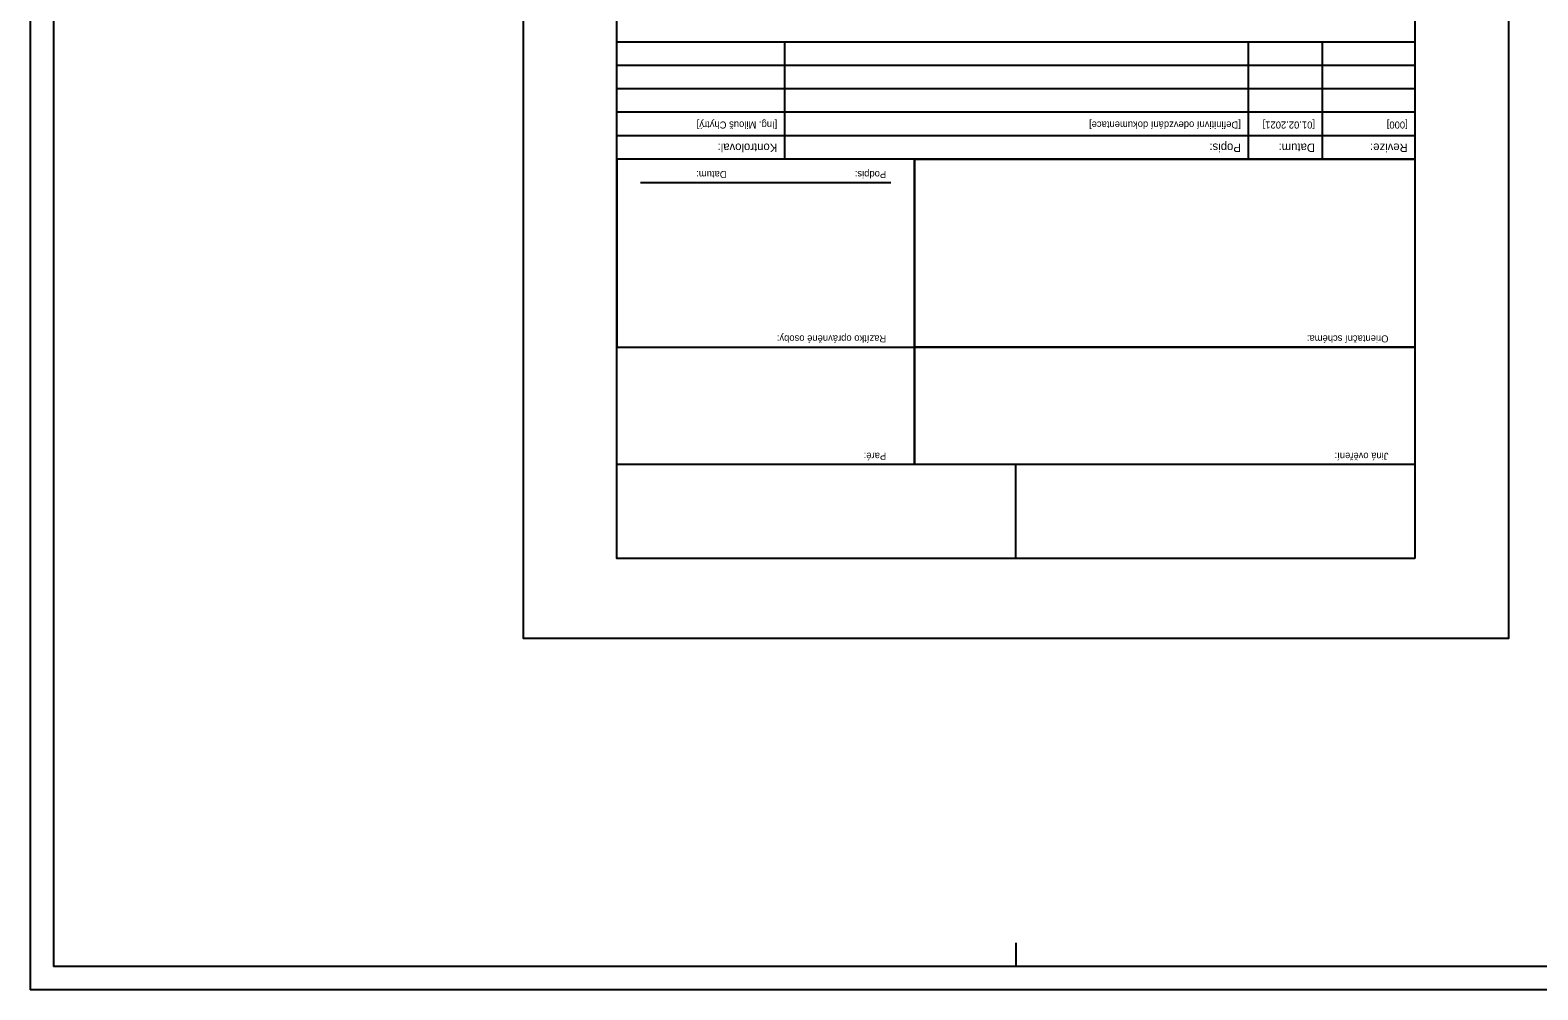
# Model space of a CAD drawing. Extents: x -751921 to -750661, y -1114881 to -1114287.
# Drawn here: x -751921.1 to -751599.9, y -1114880.7 to -1114676.3 of the extents above; entities that cross this region are included whole.
import ezdxf

# ---------------------------------------------------------------- set-up
doc = ezdxf.new("R2010")
doc.units = 0
doc.layers.add('Default', color=7, linetype='Continuous')
doc.layers.add('tisk', color=7, linetype='Continuous')

# ---------------------------------------------------------------- blocks, each defined once
blk = doc.blocks.new('ZMENY_1')
at = {"layer": 'Default'}
for p, q in [((-1502.5, 0), (-1502.5, 250)), ((-1344.5, 0), (-1344.5, 250)), ((-357, 0), (-357, 250)), ((-1700, 200), (0, 200)), ((-1700, 150), (0, 150)), ((-1700, 100), (0, 100)), ((-1700, 50), (0, 50))]:
    blk.add_line(p, q, dxfattribs=at)
blk.add_lwpolyline([(-1700, 250), (0, 250), (0, 0), (-1700, 0)], close=True, dxfattribs=at)
for s, height, p in [('Revize:', 18, (-1684.5, 216.5)), ('Datum:', 18, (-1487, 216.5)), ('Popis:', 18, (-1329, 216.5)), ('Kontroloval:', 18, (-341.5, 216.5)), ('[000]', 15, (-1684.5, 169.5)), ('[01.02.2021]', 15, (-1487, 169.5)), ('[Definitivní odevzdání dokumentace]', 15, (-1329, 169.5)), ('[Ing. Milouš Chytrý]', 15, (-341.5, 169.5))]:
    blk.add_text(s, height=height, dxfattribs=at).set_placement(p)

msp = doc.modelspace()

# ---------------------------------------------------------------- linework, layer by layer
at = {"layer": 'tisk'}
for p, q in [((-751921.09, -1114583.66), (-751921.09, -1114880.66)), ((-751916.09, -1114583.66), (-751916.09, -1114875.66)), ((-751732.74, -1114703.77), (-751732.74, -1114768.77)), ((-751737.74, -1114708.77), (-751791.09, -1114708.77)), ((-751711.09, -1114788.77), (-751711.09, -1114768.77)), ((-751711.09, -1114870.66), (-751711.09, -1114875.66)), ((-751501.09, -1114875.66), (-751916.09, -1114875.66)), ((-751711.09, -1114880.66), (-751921.09, -1114880.66)), ((-751501.09, -1114880.66), (-751711.09, -1114880.66))]:
    msp.add_line(p, q, dxfattribs=at)
for points in [[(-751606.09, -1114508.77), (-751816.09, -1114508.77), (-751816.09, -1114805.77), (-751606.09, -1114805.77)], [(-751626.09, -1114788.77), (-751796.09, -1114788.77), (-751796.09, -1114523.77), (-751626.09, -1114523.77)], [(-751796.09, -1114743.77), (-751732.74, -1114743.77), (-751732.74, -1114703.77), (-751796.09, -1114703.77)], [(-751626.09, -1114743.77), (-751732.74, -1114743.77), (-751732.74, -1114703.77), (-751626.09, -1114703.77)], [(-751732.74, -1114768.77), (-751796.09, -1114768.77), (-751796.09, -1114743.77), (-751732.74, -1114743.77)], [(-751626.09, -1114768.77), (-751732.74, -1114768.77), (-751732.74, -1114743.77), (-751626.09, -1114743.77)]]:
    msp.add_lwpolyline(points, close=True, dxfattribs=at)

# ---------------------------------------------------------------- block references
at = {"layer": 'tisk', "xscale": 0.1, "yscale": 0.10000000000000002, "rotation": 180}
msp.add_blockref('ZMENY_1', (-751796.09, -1114678.77), dxfattribs=at)

# ---------------------------------------------------------------- texts
at = {"layer": 'tisk'}
for s, p in [('Datum:', (-751772.74, -1114706.27)), ('Podpis:', (-751738.74, -1114706.27)), ('Razítko oprávněné osoby:', (-751738.74, -1114741.27)), ('Orientační schéma:', (-751631.74, -1114741.27)), ('Paré:', (-751738.74, -1114766.27)), ('Jiná ověření:', (-751631.74, -1114766.27))]:
    msp.add_text(s, height=1.5, rotation=180, dxfattribs=at).set_placement(p)

doc.saveas('drawing.dxf')
